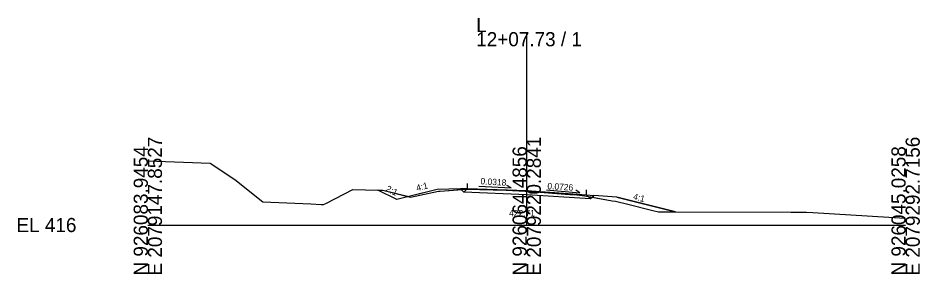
# Model space of a CAD drawing. Extents: x -26 to 10503, y -10 to 9546.
# Drawn here: x 4574.3 to 4752.8, y -9.7 to 41 of the extents above; entities that cross this region are included whole.
import ezdxf

# ---------------------------------------------------------------- set-up
doc = ezdxf.new("R2010")
doc.units = 0
for name, color, linetype in [('Default', 7, 'Continuous'), ('Exist Cross Section Cell', 7, 'Continuous'), ('Exist XS Center Line Elevation Label', 7, 'Continuous'), ('Exist XS Ground Line', 7, 'Continuous'), ('Old_Level_58', 7, 'Continuous'), ('Prop XS Ditch Slope Text', 7, 'Continuous'), ('Prop XS EOT Tick Mark', 7, 'Continuous'), ('Prop XS Finish Grade', 7, 'Continuous'), ('Prop XS Finish Grade Earthwork', 7, 'Continuous'), ('Prop XS Finish Grade Pavement', 7, 'Continuous'), ('Prop XS Pvmt Edge Slope', 7, 'Continuous'), ('Prop XS SE Text', 7, 'Continuous'), ('Prop XS Side Slope Text', 7, 'Continuous'), ('Prop XS Subgrade Earthwork', 7, 'Continuous')]:
    doc.layers.add(name, color=color, linetype=linetype)

msp = doc.modelspace()

# ---------------------------------------------------------------- linework, layer by layer
at = {"layer": 'Default'}
for points in [[(4661.99, 7.03), (4661.87, 7.16), (4657.28, 7.03), (4651.67, 5.63), (4652.02, 5.54), (4652.91, 5.73), (4657.54, 6.68), (4657.89, 6.71)], [(4651.67, 5.63), (4649.28, 5.03), (4645.5, 6.92), (4646.54, 6.9)], [(4661.99, 7.03), (4663.16, 7.13), (4670.91, 6.87), (4674.69, 6.73), (4675, 6.71), (4683.56, 6.06), (4684.94, 5.96), (4686.5, 5.81), (4688, 5.53), (4687.63, 5.17), (4675, 5.97), (4662.55, 6.48)], [(4688, 5.53), (4691.94, 4.81), (4692.58, 4.7), (4693.13, 4.57), (4694.46, 4.23), (4699.96, 2.86), (4701.07, 2.6), (4704.42, 2.59), (4692.83, 5.49), (4688.31, 5.85)]]:
    msp.add_lwpolyline(points, close=True, dxfattribs=at)
at = {"layer": 'Exist Cross Section Cell'}
for p, q in [((4675, 0), (4675, 38.19)), ((4600, 0), (4675, 0)), ((4675, 0), (4750, 0))]:
    msp.add_line(p, q, dxfattribs=at)
at = {"layer": 'Exist XS Ground Line'}
for p, q in [((4600, 12.73), (4612.34, 12.24)), ((4612.34, 12.24), (4617.21, 9)), ((4617.21, 9), (4622.77, 4.56)), ((4635.36, 4.34), (4640.55, 7.06)), ((4640.55, 7.06), (4643.06, 6.96)), ((4643.06, 6.96), (4646.54, 6.9)), ((4646.54, 6.9), (4652.02, 5.54)), ((4652.02, 5.54), (4652.91, 5.73)), ((4652.91, 5.73), (4657.54, 6.68)), ((4657.54, 6.68), (4657.89, 6.71)), ((4657.89, 6.71), (4663.16, 7.13)), ((4663.16, 7.13), (4670.91, 6.87)), ((4670.91, 6.87), (4674.69, 6.73)), ((4674.69, 6.73), (4675, 6.71)), ((4675, 6.71), (4683.56, 6.06)), ((4683.56, 6.06), (4684.94, 5.96)), ((4684.94, 5.96), (4686.5, 5.81)), ((4686.5, 5.81), (4691.94, 4.81)), ((4622.77, 4.56), (4632.29, 4.19)), ((4632.29, 4.19), (4634.3, 4.07)), ((4634.3, 4.07), (4634.74, 4.06)), ((4634.74, 4.06), (4635.36, 4.34)), ((4691.94, 4.81), (4692.58, 4.7)), ((4692.58, 4.7), (4693.13, 4.57)), ((4693.13, 4.57), (4694.46, 4.23)), ((4694.46, 4.23), (4699.96, 2.86)), ((4699.96, 2.86), (4701.07, 2.6)), ((4701.07, 2.6), (4727.31, 2.52)), ((4727.31, 2.52), (4730.36, 2.53)), ((4730.36, 2.53), (4731.66, 2.51)), ((4731.66, 2.51), (4746.68, 1.58)), ((4746.68, 1.58), (4750, 1.38))]:
    msp.add_line(p, q, dxfattribs=at)
at = {"layer": 'Prop XS EOT Tick Mark'}
for p, q in [((4663.28, 7.2), (4663.28, 8.2)), ((4686.83, 5.97), (4686.83, 6.97))]:
    msp.add_line(p, q, dxfattribs=at)
at = {"layer": 'Prop XS Finish Grade'}
for p, q in [((4663.28, 7.2), (4661.87, 7.16)), ((4686.83, 5.97), (4688.31, 5.85))]:
    msp.add_line(p, q, dxfattribs=at)
at = {"layer": 'Prop XS Finish Grade Earthwork'}
for p, q in [((4661.87, 7.16), (4657.28, 7.03)), ((4649.28, 5.03), (4645.5, 6.92)), ((4657.28, 7.03), (4649.28, 5.03)), ((4692.83, 5.49), (4688.31, 5.85)), ((4692.83, 5.49), (4704.42, 2.59))]:
    msp.add_line(p, q, dxfattribs=at)
at = {"layer": 'Prop XS Finish Grade Pavement'}
for p, q in [((4663.28, 7.2), (4675, 6.83)), ((4675, 6.83), (4686.83, 5.97))]:
    msp.add_line(p, q, dxfattribs=at)
at = {"layer": 'Prop XS Pvmt Edge Slope'}
for p, q in [((4663.27, 7.2), (4662.55, 6.48)), ((4686.83, 5.97), (4687.63, 5.17))]:
    msp.add_line(p, q, dxfattribs=at)
at = {"layer": 'Prop XS SE Text'}
for points in [[(4665.54, 7.69), (4671.89, 7.38), (4671.04, 7.84)], [(4678.89, 6.95), (4685.54, 6.38), (4684.7, 6.88)]]:
    msp.add_lwpolyline(points, dxfattribs=at)
at = {"layer": 'Prop XS Subgrade Earthwork'}
for p, q in [((4662.55, 6.48), (4661.87, 7.16)), ((4675, 5.97), (4662.55, 6.48)), ((4687.63, 5.17), (4675, 5.97)), ((4687.63, 5.17), (4688.31, 5.85))]:
    msp.add_line(p, q, dxfattribs=at)

# ---------------------------------------------------------------- texts
at = {"layer": 'Exist Cross Section Cell'}
for s, p in [('L', (4665, 38.19)), ('12+07.73 / 1', (4665, 35.39)), ('EL 416', (4574, -1.4))]:
    msp.add_text(s, height=2.8, dxfattribs=at).set_placement(p)
for s, p in [('E 2079147.8527', (4602.8, -10)), ('E 2079220.2841', (4677.8, -10)), ('E 2079292.7156', (4752.8, -10)), ('N 926083.9454', (4600, -10)), ('N 926064.4856', (4675, -10)), ('N 926045.0258', (4750, -10))]:
    msp.add_text(s, height=2.8, rotation=90, dxfattribs=at).set_placement(p)
at = {"layer": 'Exist XS Center Line Elevation Label'}
msp.add_text('422.71', height=1.25, rotation=360, dxfattribs=at).set_placement((4671.51, 1.73))
at = {"layer": 'Old_Level_58'}
for p in [(4657.28, 6.99), (4692.83, 5.45)]:
    msp.add_text('Case1', height=0.04, dxfattribs=at).set_placement(p)
at = {"layer": 'Prop XS Ditch Slope Text'}
for rotation, p in [(14.0362, (4653.29, 6.7)), (345.9639, (4695.96, 5.09))]:
    msp.add_text('4:1', height=1.25, rotation=rotation, dxfattribs=at).set_placement(p)
at = {"layer": 'Prop XS SE Text'}
for s, p in [('0.0318', (4665.82, 8.08)), ('0.0726', (4679.06, 7.12))]:
    msp.add_text(s, height=1.25, rotation=356.3381, dxfattribs=at).set_placement(p)
at = {"layer": 'Prop XS Side Slope Text'}
msp.add_text('2:1', height=1.25, rotation=333.4349, dxfattribs=at).set_placement((4646.99, 6.79))

doc.saveas('drawing.dxf')
